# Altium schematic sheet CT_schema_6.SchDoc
size 156 x 177 mm
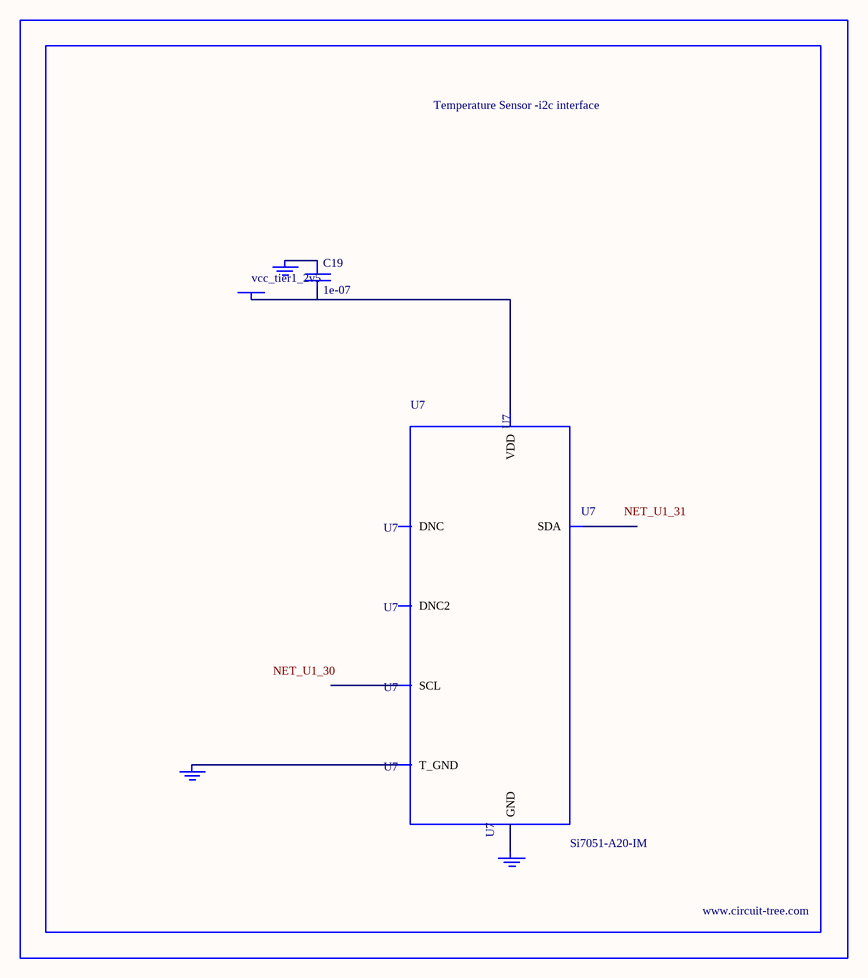
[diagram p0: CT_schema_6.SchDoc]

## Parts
BORDER5  (no value)
C19  1e-07  [C0402]
GND_INSTANCE_5_0  (no value)
GND_INSTANCE_5_1  (no value)
GND_INSTANCE_5_2  (no value)
POWER_INSTANCE_5_0  vcc_tier1_2v5
U7  Si7051-A20-IM  [DFN-6]

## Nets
NetC19_1: C19.1 GND_INSTANCE_5_0.0(GND)
NetC19_2: C19.2 POWER_INSTANCE_5_0.0(PWR) U7.5(VDD)
NetGND_INSTANCE_5_1_0: GND_INSTANCE_5_1.0(GND) U7.7(T_GND)
NetGND_INSTANCE_5_2_0: GND_INSTANCE_5_2.0(GND) U7.2(GND)

Not connected (* = marked no-connect by the designer): U7 1(SDA) 3(DNC) 4(DNC2) 6(SCL)

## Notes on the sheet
- Labels drawn without touching a wire or pin: NET_U1_30, NET_U1_31

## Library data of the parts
BORDER5 = BORDER_PAGE5
C19 = C0402C104K3RACTU
GND_INSTANCE_5_0-GND_INSTANCE_5_2 = GND
POWER_INSTANCE_5_0 = PWR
